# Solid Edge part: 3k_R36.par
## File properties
Author: Türk
Template: Iso Part.par
Last saved by: Türk
Revision: 9
Application: Solid Edge
Accuracy: 0,990
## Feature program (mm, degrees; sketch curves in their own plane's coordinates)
pattern "PatternOccurrence_1"  XOffset = 8 deg
pattern "PatternOccurrence_2"  XOffset = 8 deg
pattern "PatternOccurrence_3"  XCount = 30; XOffset = 12 deg
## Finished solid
Body 1: solid body, 424 faces, 1262 edges, 840 vertices.
  Faces by surface: plane 273, cylinder 151
  Edges by curve: line 960, circle 302
Bounding box of the edges (mm): 79.981 x 35.000 x 79.936, from (-39.9907, -5, -39.9363) to (39.9907, 30, 40).
Cylindrical faces by radius (mm): R1.25 x30, R14 x1, R15 x30, R36 x45, R40 x45
Planar faces by outward normal: +x 1, +y 1, -x 1, -y 2, -z 2, oblique 266
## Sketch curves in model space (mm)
line (1.25, 0, -36) -> (1.2492, 0, -35.9783)
line (-1.2492, 0, -35.9783) -> (-1.25, 0, -36)
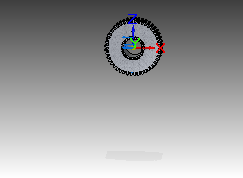
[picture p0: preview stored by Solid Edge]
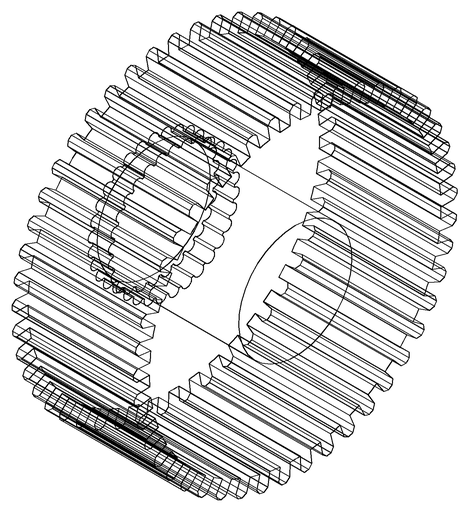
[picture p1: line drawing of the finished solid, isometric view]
